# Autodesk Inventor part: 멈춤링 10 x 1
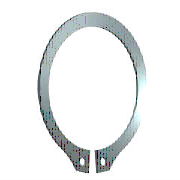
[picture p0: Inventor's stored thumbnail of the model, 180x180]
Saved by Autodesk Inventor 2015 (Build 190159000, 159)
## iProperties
IsCustomPart: 0
Created: 2015-11
Part Number: 멈춤링 10 x 1
Material: 스테인리스강
Description: 리테이닝 링(C형)
Document SubType Name: Modeling
Standard: KS B 1336
Designer: mdu
Standards Organization: KS
Language: ko-KR
Size Designation: 10 x 1
Categories: <MemberInstance><Categories><Category DisplayName="샤프트 부품" InternalName="7f7aeb1f-a693-4053-b835-cee3144e0d98" Mnemonic="SHFT"><Category DisplayName="써클립" Inter
Density: 1 g/cm^3
Appearance: 반광택
Author: mdu
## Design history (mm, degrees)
sketch "스케치1"
  geometry: L1 (-6, 0)-(6, 0) reference; L2 (0, 20.189)-(0, -80.536) reference; L3 (-48.09, 0)-(48.09, 0) reference; L4 (-0.3, -9.791)-(-0.3, -12.791); L5 (-0.3, -6.54)-(-0.3, -13.29); L6 (-2.795, 1.6)-(3.672, 1.6); L7 (0.3, -6.54)-(0.3, -13.29); L8 (0.3, -9.791)-(0.3, -12.791); C1 r 0.6 at (-1.2, -11.486); C2 r 0.6 at (1.2, -11.486); A1 r 4.8 centre (0, -5) between (0.3, -9.791) and (-0.3, -9.791); A2 r 6.2 centre (0, -4.6) between (2.988, -10.033) and (-2.988, -10.033); A3 r 7.796 centre (0, -5) between (-1.418, -12.666) and (-0.3, -12.791); A4 r 1.2 centre (-1.2, -11.486) between (-2.383, -11.285) and (-1.418, -12.666); A5 r 1.2 centre (-3.566, -11.084) between (-2.383, -11.285) and (-2.988, -10.033); A6 r 1.2 centre (3.566, -11.084) between (2.988, -10.033) and (2.383, -11.285); A7 r 1.2 centre (1.2, -11.486) between (1.418, -12.666) and (2.383, -11.285); A8 r 7.796 centre (0, -5) between (0.3, -12.791) and (1.418, -12.666)
  constraints: 16 point on circle, 12 end point, 10 centre point, 9 symmetric about line, 5 point on line, 4 tangent, 3 coincident, 2 horizontal, 1 perpendicular, 1 vertical, 5 other
  dimensions: "d0" = 9.6 diameter of A1 (= ND); "d1" = 3 distance of L4.end L4.start (= SRB2); "d6" = 0.3 distance between parallel lines of L2 L5 (= 0.25 x SD5); "d7" = 1.6 distance between parallel lines of L6 L3 (= SRB1); "d8" = 0.4 distance of A1.centre A2.centre (= 0.25 x SRB1); "d9" = 1.2 radius of A4 (= SD5); "d10" = 1.2 radius of A5 (= SD5); "d11" = 0.9 distance from line of L4 A4.centre (= 0.75 x SD5); "d12" = 1.2 diameter of C1 (= SD5); "d13" = 1.2 diameter of C2 (= SD5); "d14" = 5 distance from line of A1.centre L1 (= 0.5 x WD)
extrude "본체" new body sketch "스케치1" distance "d2" = 1 (= SD); taper "d3" = 0 deg
workaxis "Work Axis1"
workplane "Work Plane1"
body "Solid1"
other parameters: "SD" = 1 [user parameter; used in 1 equation term], "SRB1" = 1.6 [user parameter; used in 2 equation terms], "ND" = 9.6 [user parameter; used in 1 equation term], "SRB2" = 3 [user parameter; used in 1 equation term], "SD5" = 1.2 [user parameter; used in 6 equation terms], "d15" = 0, "d16" = 0, "d17" = 0, "d41" = 0, "d42" = 0, "SD3" = 9.3 [user parameter], "WDMAX" = 11 [user parameter]
